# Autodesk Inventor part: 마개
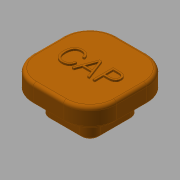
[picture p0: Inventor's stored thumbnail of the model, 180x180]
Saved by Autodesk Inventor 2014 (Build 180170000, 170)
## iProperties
Created: 2018-03
Part Number: 마개
Material: 고무
Document SubType Name: Modeling
Designer: mduedu
Density: 1 g/cm^3
Appearance: 주황색
Author: mduedu
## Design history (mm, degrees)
sketch "스케치1"
  geometry: L1 (12.5, 12.5)-(-12.5, 12.5); L2 (-12.5, 12.5)-(-12.5, -12.5); L3 (-12.5, -12.5)-(12.5, -12.5); L4 (12.5, -12.5)-(12.5, 12.5); L5 (12.5, 12.5)-(-12.5, -12.5); L6 (-12.5, 12.5)-(12.5, -12.5); 1 further point
  constraints: 12 end point, 2 midpoint, 2 parallel, 1 horizontal, 1 perpendicular
  dimensions: "d0" = 25 distance of L3.end L2.end; "d1" = 25 distance of L2.end L1.end
extrude "돌출1" new body sketch "스케치1" distance "d2" = 6; taper "d3" = 0 deg
fillet "모깎기1" dims "d4" = 8
fillet "모깎기2" dims "d5" = 1
sketch "스케치2"
  geometry: L1 (4.5, -12.5)-(-4.5, -12.5) reference; L2 (12.5, 4.5)-(12.5, -4.5) reference; L3 (-4.5, 12.5)-(4.5, 12.5) reference; L4 (-12.5, -4.5)-(-12.5, 4.5) reference; L5 (7.5, 4.5)-(7.5, -4.5); L6 (4.5, -7.5)-(-4.5, -7.5); L7 (-7.5, -4.5)-(-7.5, 4.5); L8 (-4.5, 7.5)-(4.5, 7.5); A1 r 8 centre (-4.5, -4.5) between (-12.5, -4.5) and (-4.5, -12.5) reference; A2 r 8 centre (4.5, -4.5) between (4.5, -12.5) and (12.5, -4.5) reference; A3 r 8 centre (4.5, 4.5) between (12.5, 4.5) and (4.5, 12.5) reference; A4 r 8 centre (-4.5, 4.5) between (-4.5, 12.5) and (-12.5, 4.5) reference; A5 r 3 centre (4.5, 4.5) between (7.5, 4.5) and (4.5, 7.5); A6 r 3 centre (4.5, -4.5) between (4.5, -7.5) and (7.5, -4.5); A7 r 3 centre (-4.5, -4.5) between (-7.5, -4.5) and (-4.5, -7.5); A8 r 3 centre (-4.5, 4.5) between (-4.5, 7.5) and (-7.5, 4.5); 1 further point
  constraints: 8 end point, 8 point on circle, 4 centre point, 7 other
  dimensions: "d6" = 5 distance between parallel lines of L8 L3
extrude "돌출2" join sketch "스케치2" distance "d7" = 6; taper "d8" = 0 deg
sketch "스케치3"
  geometry: L1 (4.5, 7.5)-(-4.5, 7.5) reference; L2 (-7.5, 4.5)-(-7.5, -4.5) reference; L3 (-4.5, -7.5)-(4.5, -7.5) reference; L4 (7.5, -4.5)-(7.5, 4.5) reference; L5 (-4.5, 5)-(4.5, 5); L6 (5, 4.5)-(5, -4.5); L7 (4.5, -5)-(-4.5, -5); L8 (-5, -4.5)-(-5, 4.5); A1 r 3 centre (4.5, 4.5) between (7.5, 4.5) and (4.5, 7.5) reference; A2 r 3 centre (-4.5, 4.5) between (-4.5, 7.5) and (-7.5, 4.5) reference; A3 r 3 centre (-4.5, -4.5) between (-7.5, -4.5) and (-4.5, -7.5) reference; A4 r 3 centre (4.5, -4.5) between (4.5, -7.5) and (7.5, -4.5) reference; A5 r 0.5 centre (4.5, 4.5) between (5, 4.5) and (4.5, 5); A6 r 0.5 centre (4.5, -4.5) between (4.5, -5) and (5, -4.5); A7 r 0.5 centre (-4.5, -4.5) between (-5, -4.5) and (-4.5, -5); A8 r 0.5 centre (-4.5, 4.5) between (-4.5, 5) and (-5, 4.5); 1 further point
  constraints: 8 end point, 8 point on circle, 4 centre point, 7 other
  dimensions: "d9" = 2.5 distance between parallel lines of L5 L1
extrude "돌출3" cut sketch "스케치3" stored distance "d10" = 10; taper "d11" = 0 deg
fillet "모깎기3" dims "d12" = 1
sketch "스케치4"
  geometry: L1 (7.5, 4.5)-(7.5, -4.5) reference; L2 (4.5, -7.5)-(-4.5, -7.5) reference; L3 (-7.5, -4.5)-(-7.5, 4.5) reference; L4 (-4.5, 7.5)-(4.5, 7.5) reference; L5 (4.5, -12.5)-(-4.5, -12.5) reference; L6 (12.5, 4.5)-(12.5, -4.5) reference; L7 (-4.5, 12.5)-(4.5, 12.5) reference; L8 (-12.5, -4.5)-(-12.5, 4.5) reference; L9 (11.5, 4.5)-(11.5, -4.5); L10 (4.5, -11.5)-(-4.5, -11.5); L11 (-11.5, -4.5)-(-11.5, 4.5); L12 (-4.5, 11.5)-(4.5, 11.5); A1 r 3 centre (4.5, -4.5) between (4.5, -7.5) and (7.5, -4.5) reference; A2 r 3 centre (-4.5, -4.5) between (-7.5, -4.5) and (-4.5, -7.5) reference; A3 r 3 centre (-4.5, 4.5) between (-4.5, 7.5) and (-7.5, 4.5) reference; A4 r 3 centre (4.5, 4.5) between (7.5, 4.5) and (4.5, 7.5) reference; A5 r 8 centre (-4.5, -4.5) between (-12.5, -4.5) and (-4.5, -12.5) reference; A6 r 8 centre (4.5, -4.5) between (4.5, -12.5) and (12.5, -4.5) reference; A7 r 8 centre (4.5, 4.5) between (12.5, 4.5) and (4.5, 12.5) reference; A8 r 8 centre (-4.5, 4.5) between (-4.5, 12.5) and (-12.5, 4.5) reference; A9 r 7 centre (4.5, 4.5) between (11.5, 4.5) and (4.5, 11.5); A10 r 7 centre (4.5, -4.5) between (4.5, -11.5) and (11.5, -4.5); A11 r 7 centre (-4.5, -4.5) between (-11.5, -4.5) and (-4.5, -11.5); A12 r 7 centre (-4.5, 4.5) between (-4.5, 11.5) and (-11.5, 4.5); 1 further point
  constraints: 8 end point, 8 point on circle, 4 centre point, 7 other
  dimensions: "d13" = 1 distance between parallel lines of L12 L7
extrude "돌출4" cut sketch "스케치4" distance "d14" = 1; taper "d15" = 0 deg
chamfer "모따기1" distance "d16" = 0.5; stored, may be unused: second distance "d17" = 2, angle "d18" = 45 deg
sketch "스케치5"
  geometry: 2 further points
  constraints: 1 coincident, 1 other
feature "엠보싱1" sketch "스케치5" dims "d0" = 25, "d1" = 25, "d19" = 0.5, "d20" = 0
node "솔리드1"
node "투영된 루프1"
node "투영된 루프2"
node "투영된 루프3"
